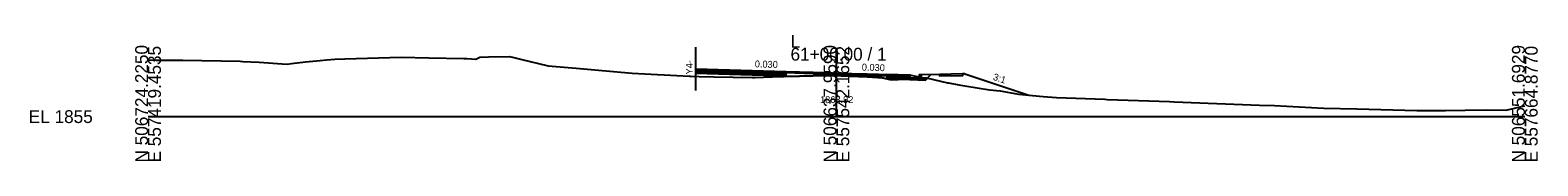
# Model space of a CAD drawing. Extents: x -26 to 4603, y -10 to 4703.
# Drawn here: x 2474.3 to 2802.8, y 440.3 to 467.8 of the extents above; entities that cross this region are included whole.
import ezdxf

# ---------------------------------------------------------------- set-up
doc = ezdxf.new("R2010")
doc.units = 0
for name, color, linetype in [('Default', 7, 'Continuous'), ('Exist Cross Section Cell', 7, 'Continuous'), ('Exist XS Ground Line', 7, 'Continuous'), ('Prop CMT Pvmt Course 1', 7, 'Continuous'), ('Prop CMT Pvmt Course 2', 7, 'Continuous'), ('Prop CMT Pvmt Course 3', 7, 'Continuous'), ('Prop CMT Pvmt Milling', 7, 'Continuous'), ('Prop CMT Shear Line', 7, 'Continuous'), ('Prop CMT Shld Paved Course 2', 7, 'Continuous'), ('Prop CMT Subgrade Earthwork', 7, 'Continuous'), ('Prop Conc 4in Sidewalk', 7, 'Continuous'), ('Prop Conc Curb and Gutter', 7, 'Continuous'), ('Prop Corridor Mesh Bottom', 7, 'Continuous'), ('Prop XS Finish Grade', 7, 'Continuous'), ('Prop XS Label Text', 7, 'Continuous'), ('Prop XS Shear Point Element', 7, 'Continuous'), ('Prop XS Shear Point Label', 7, 'Continuous'), ('Prop XS SS Elevation Text', 7, 'Continuous')]:
    doc.layers.add(name, color=color, linetype=linetype)

msp = doc.modelspace()

# ---------------------------------------------------------------- linework, layer by layer
at = {"layer": 'Exist Cross Section Cell'}
for p, q in [((2650, 450), (2650, 465)), ((2500, 450), (2650, 450)), ((2650, 450), (2800, 450))]:
    msp.add_line(p, q, dxfattribs=at)
at = {"layer": 'Exist XS Ground Line'}
msp.add_lwpolyline([(2500, 462.36), (2501.76, 462.31), (2507.57, 462.3), (2520.1, 462.07), (2520.66, 462.01), (2524.2, 461.83), (2529.23, 461.52), (2530.31, 461.46), (2531.24, 461.57), (2534.34, 461.97), (2537.53, 462.25), (2538.89, 462.36), (2540.67, 462.51), (2542.9, 462.58), (2555.12, 462.94), (2561.18, 462.8), (2568.8, 462.69), (2569.51, 462.64), (2571.42, 462.54), (2572.12, 462.85), (2572.3, 462.95), (2574.15, 463), (2578.79, 463.09), (2579.68, 462.88), (2581.15, 462.51), (2587.19, 461.08), (2593.25, 460.53), (2605.49, 459.44), (2617.96, 458.82), (2620.07, 458.74), (2623.27, 458.68), (2631.71, 458.52), (2632.21, 458.52), (2634.11, 458.61), (2636.06, 458.68), (2638.54, 458.77), (2644.91, 458.86), (2649.17, 458.95), (2656.72, 458.63), (2658.97, 458.53), (2659.19, 458.51), (2659.97, 458.46), (2661.28, 458.17), (2662.03, 458), (2663.47, 458.12), (2664.24, 458.15), (2665.32, 458.31), (2665.77, 458.41), (2667.15, 458.42), (2669.63, 458.45), (2674.19, 457.37), (2674.41, 457.34), (2676.64, 456.93), (2678.01, 456.74), (2683.35, 455.86), (2685.65, 455.58), (2689.65, 454.9), (2695.03, 454.38), (2697.96, 454.18), (2708.52, 453.78), (2709.01, 453.76), (2711.29, 453.67), (2722.56, 453.26), (2723.62, 453.21), (2742.18, 452.51), (2745.42, 452.41), (2756.24, 451.86), (2763.4, 451.71), (2776.5, 451.32), (2782.74, 451.3), (2787.01, 451.4), (2791.7, 451.45), (2795.91, 451.4), (2799.25, 452.17), (2800, 452.35)], dxfattribs=at)
at = {"layer": 'Prop CMT Pvmt Course 1'}
for points in [[(2619.36, 460.42), (2639, 459.83), (2639, 459.83), (2639, 459.58), (2619.36, 460.17), (2619.36, 460.17), (2619.36, 460.42), (2619.36, 460.42), (2619.36, 460.42)], [(2650, 459.5), (2650, 459.5), (2650, 459.5), (2650, 458.92), (2650, 458.92), (2649.17, 458.95), (2649.17, 458.95), (2644.91, 458.86), (2644.91, 458.86), (2639, 458.77), (2639, 459.83), (2639, 459.83), (2644.91, 459.66), (2644.91, 459.66), (2649.17, 459.53), (2649.17, 459.53), (2650, 459.5)], [(2661, 459.17), (2661, 459.17), (2661, 459.17), (2661, 458.23), (2659.97, 458.46), (2659.97, 458.46), (2659.97, 458.46), (2659.19, 458.51), (2659.19, 458.51), (2658.97, 458.53), (2656.72, 458.63), (2656.72, 458.63), (2650, 458.92), (2650, 458.92), (2650, 459.5), (2650, 459.5), (2650, 459.5), (2656.72, 459.3), (2656.72, 459.3), (2658.97, 459.24), (2659.19, 459.23), (2659.19, 459.23), (2659.97, 459.21), (2659.97, 459.21), (2661, 459.17)], [(2661, 459.17), (2661, 459.17), (2661, 459.17), (2661, 458.92), (2661, 458.92), (2666, 458.77), (2666, 459.02), (2666, 459.02), (2661, 459.17)]]:
    msp.add_lwpolyline(points, dxfattribs=at)
at = {"layer": 'Prop CMT Pvmt Course 2'}
for points in [[(2619.36, 460.17), (2639, 459.58), (2639, 459.58), (2639, 459.25), (2619.36, 459.84), (2619.36, 459.84), (2619.36, 460.17), (2619.36, 460.17), (2619.36, 460.17)], [(2661, 458.92), (2661, 458.92), (2661, 458.92), (2661, 458.59), (2661, 458.59), (2666, 458.44), (2666, 458.77), (2666, 458.77), (2661, 458.92)]]:
    msp.add_lwpolyline(points, dxfattribs=at)
at = {"layer": 'Prop CMT Pvmt Course 3'}
for points in [[(2619.36, 459.84), (2639, 459.25), (2639, 459.25), (2639, 458.88), (2619.36, 459.47), (2619.36, 459.47), (2619.36, 459.84), (2619.36, 459.84), (2619.36, 459.84)], [(2661, 458.59), (2661, 458.59), (2661, 458.59), (2661, 458.22), (2661, 458.22), (2666, 458.07), (2666, 458.44), (2666, 458.44), (2661, 458.59)], [(2666, 458.44), (2666, 458.44), (2666, 458.44), (2666, 458.07), (2666, 458.07), (2669.38, 457.97), (2669, 458.35), (2669, 458.35), (2666, 458.44)]]:
    msp.add_lwpolyline(points, dxfattribs=at)
at = {"layer": 'Prop CMT Pvmt Milling'}
for points in [[(2639, 458.77), (2644.91, 458.86), (2644.91, 458.86), (2649.17, 458.95), (2649.17, 458.95), (2650, 458.92), (2650, 458.92)], [(2661, 458.23), (2659.97, 458.46), (2659.97, 458.46), (2659.97, 458.46), (2659.19, 458.51), (2659.19, 458.51), (2658.97, 458.53), (2656.72, 458.63), (2656.72, 458.63), (2650, 458.92), (2650, 458.92)]]:
    msp.add_lwpolyline(points, dxfattribs=at)
at = {"layer": 'Prop CMT Shld Paved Course 2'}
for points in [[(2650, 459.25), (2650, 459.25), (2650, 459.25), (2650, 458.92), (2649.54, 458.94), (2649.54, 458.94), (2649.17, 458.95), (2649.17, 458.95), (2649.17, 458.95), (2649.07, 458.95), (2649.07, 458.95), (2644.91, 458.86), (2644.91, 458.86), (2639, 458.77), (2639, 459.58), (2639, 459.58), (2644.91, 459.41), (2644.91, 459.41), (2649.17, 459.28), (2649.17, 459.28), (2650, 459.25)], [(2661, 458.92), (2661, 458.92), (2661, 458.92), (2661, 458.23), (2659.97, 458.46), (2659.97, 458.46), (2659.97, 458.46), (2659.19, 458.51), (2659.19, 458.51), (2658.97, 458.53), (2656.72, 458.63), (2656.72, 458.63), (2650, 458.92), (2650, 458.92), (2650, 459.25), (2650, 459.25), (2650, 459.25), (2656.72, 459.05), (2656.72, 459.05), (2658.97, 458.99), (2659.19, 458.98), (2659.19, 458.98), (2659.97, 458.96), (2659.97, 458.96), (2661, 458.92)]]:
    msp.add_lwpolyline(points, dxfattribs=at)
at = {"layer": 'Prop CMT Subgrade Earthwork'}
for points in [[(2619.36, 459.47), (2639, 458.88)], [(2669.38, 457.97), (2661, 458.22), (2661, 458.22)], [(2670.58, 459.17), (2670.58, 459.17), (2669.38, 457.97)]]:
    msp.add_lwpolyline(points, dxfattribs=at)
at = {"layer": 'Prop Conc 4in Sidewalk'}
msp.add_lwpolyline([(2677.5, 459.3), (2672.5, 459.2), (2672.5, 459.2), (2672.49, 458.87), (2677.51, 458.97), (2677.51, 458.97), (2677.5, 459.3), (2677.5, 459.3), (2677.5, 459.3)], dxfattribs=at)
at = {"layer": 'Prop Conc Curb and Gutter'}
msp.add_lwpolyline([(2666, 459.02), (2666, 459.02), (2666, 459.02), (2666, 458.44), (2666, 458.44), (2668.5, 458.37), (2668.5, 459.12), (2668.5, 459.12), (2668, 459.12), (2668, 459.12), (2668, 459.12), (2668, 458.62), (2666, 459.02)], dxfattribs=at)
at = {"layer": 'Prop Corridor Mesh Bottom'}
msp.add_lwpolyline([(2666, 459.02), (2666, 458.77)], dxfattribs=at)
at = {"layer": 'Prop XS Finish Grade'}
for points in [[(2672.5, 459.2), (2672.5, 459.2), (2668.5, 459.12)], [(2678, 459.31), (2678, 459.31), (2677.5, 459.3)], [(2678, 459.31), (2691.89, 454.69)]]:
    msp.add_lwpolyline(points, dxfattribs=at)
at = {"layer": 'Prop XS Shear Point Element'}
msp.add_line((2619.36, 455.66), (2619.36, 465.15), dxfattribs=at)

# ---------------------------------------------------------------- texts
at = {"layer": 'Default'}
msp.add_text('-', height=0.0001, dxfattribs=at).set_placement((2500, 450))
at = {"layer": 'Exist Cross Section Cell'}
for s, p in [('L', (2640, 465)), ('61+00.00 / 1', (2640, 462.2)), ('EL 1855', (2474, 448.6))]:
    msp.add_text(s, height=2.8, dxfattribs=at).set_placement(p)
for s, p in [('N 506724.2250', (2500, 440)), ('E 557419.4535', (2502.8, 440)), ('N 506637.9590', (2650, 440)), ('E 557542.1652', (2652.8, 440)), ('N 506551.6929', (2800, 440)), ('E 557664.8770', (2802.8, 440))]:
    msp.add_text(s, height=2.8, rotation=90, dxfattribs=at).set_placement(p)
at = {"layer": 'Prop CMT Shear Line'}
for p in [(2619.36, 460.42), (2650, 459.5), (2665.99, 459.02), (2665.99, 459.02), (2667.99, 458.62), (2672.5, 459.2), (2677.5, 459.3), (2678, 459.31), (2691.89, 454.68)]:
    msp.add_text('X', height=0.0025, dxfattribs=at).set_placement(p)
at = {"layer": 'Prop XS Label Text'}
for s, rotation, p in [('0.030', 358.2816, (2632.19, 460.74)), ('0.030', 358.2816, (2655.51, 460.04)), ('3:1', 341.5668, (2684, 458.05))]:
    msp.add_text(s, height=1.5, rotation=rotation, dxfattribs=at).set_placement(p)
at = {"layer": 'Prop XS Shear Point Label'}
msp.add_text('-Y4-', height=1.5, rotation=90, dxfattribs=at).set_placement((2618.69, 458.52))
at = {"layer": 'Prop XS SS Elevation Text'}
msp.add_text('1863.92', height=1.5, dxfattribs=at).set_placement((2646.43, 452.94))

doc.saveas('drawing.dxf')
